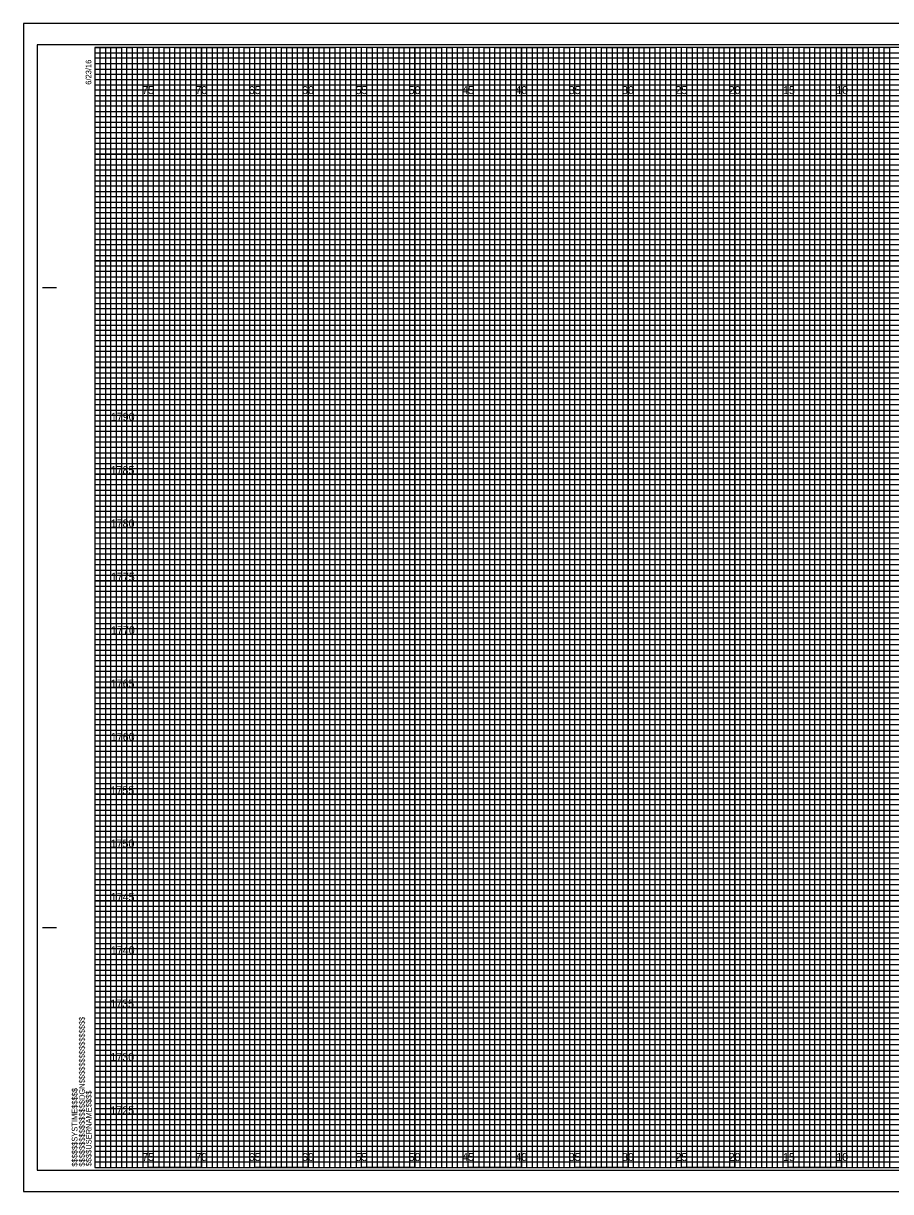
# Model space of a CAD drawing. Extents: x -7 to 162, y -2 to 547.
# Drawn here: x -6.7 to 74.6, y 107.7 to 217.2 of the extents above; entities that cross this region are included whole.
import ezdxf

# ---------------------------------------------------------------- set-up
doc = ezdxf.new("R2010")
doc.units = 0
for name, color, linetype in [('Prop XS Gore Control Minimum', 7, 'Continuous'), ('Prop XS Shoulder Borrow Shape', 7, 'Continuous'), ('Raster_Level_0', 7, 'Continuous'), ('Scratch_Level_3', 7, 'Continuous'), ('Sheet Cross Section CELL', 7, 'Continuous'), ('Sheet Cross Section Grid Minor 1 CELL', 7, 'Continuous'), ('Sheet Cross Section Grid Minor 2 CELL', 7, 'Continuous'), ('Sheet Cutting Line CELL', 7, 'Continuous'), ('Sheet DOT Grid CELL', 7, 'Continuous'), ('Sheet Plot Border Inside CELL', 7, 'Continuous'), ('Sheet Plot Border Outside CELL', 7, 'Continuous')]:
    doc.layers.add(name, color=color, linetype=linetype)

msp = doc.modelspace()

# ---------------------------------------------------------------- linework, layer by layer
at = {"layer": 'Prop XS Gore Control Minimum'}
for p, q in [((5, 215), (0, 215)), ((5, 110), (5, 215)), ((15, 215), (10, 215)), ((10, 215), (10, 110)), ((15, 110), (15, 215)), ((25, 215), (20, 215)), ((20, 215), (20, 110)), ((25, 110), (25, 215)), ((35, 215), (30, 215)), ((30, 215), (30, 110)), ((35, 110), (35, 215)), ((45, 215), (40, 215)), ((40, 215), (40, 110)), ((45, 110), (45, 215)), ((55, 215), (50, 215)), ((50, 215), (50, 110)), ((55, 110), (55, 215)), ((65, 215), (60, 215)), ((60, 215), (60, 110)), ((65, 110), (65, 215)), ((75, 215), (70, 215)), ((70, 215), (70, 110)), ((10, 110), (5, 110)), ((20, 110), (15, 110)), ((30, 110), (25, 110)), ((40, 110), (35, 110)), ((50, 110), (45, 110)), ((60, 110), (55, 110)), ((70, 110), (65, 110))]:
    msp.add_line(p, q, dxfattribs=at)
for points in [[(0, 210), (160, 210), (160, 205), (0, 205)], [(0, 200), (160, 200), (160, 195), (0, 195)], [(0, 190), (160, 190), (160, 185), (0, 185)], [(0, 180), (160, 180), (160, 175), (0, 175)], [(0, 170), (160, 170), (160, 165), (0, 165)], [(0, 160), (160, 160), (160, 155), (0, 155)], [(0, 150), (160, 150), (160, 145), (0, 145)], [(0, 140), (160, 140), (160, 135), (0, 135)], [(0, 130), (160, 130), (160, 125), (0, 125)], [(0, 120), (160, 120), (160, 115), (0, 115)]]:
    msp.add_lwpolyline(points, dxfattribs=at)
at = {"layer": 'Prop XS Shoulder Borrow Shape'}
for points in [[(0, 215), (2.5, 215), (2.5, 110), (7.5, 110), (7.5, 215), (12.5, 215), (12.5, 110), (17.5, 110), (17.5, 215), (22.5, 215), (22.5, 110), (27.5, 110), (27.5, 215), (32.5, 215), (32.5, 110), (37.5, 110), (37.5, 215), (42.5, 215), (42.5, 110), (47.5, 110), (47.5, 215), (52.5, 215), (52.5, 110), (57.5, 110), (57.5, 215), (62.5, 215), (62.5, 110), (67.5, 110), (67.5, 215), (72.5, 215), (72.5, 110), (77.5, 110)], [(0, 212.5), (137.5, 212.5)], [(0, 202.5), (160, 202.5), (160, 207.5), (0, 207.5)], [(0, 192.5), (160, 192.5), (160, 197.5), (0, 197.5)], [(0, 182.5), (160, 182.5), (160, 187.5), (0, 187.5)], [(0, 172.5), (160, 172.5), (160, 177.5), (0, 177.5)], [(0, 162.5), (160, 162.5), (160, 167.5), (0, 167.5)], [(0, 152.5), (160, 152.5), (160, 157.5), (0, 157.5)], [(0, 142.5), (160, 142.5), (160, 147.5), (0, 147.5)], [(0, 132.5), (160, 132.5), (160, 137.5), (0, 137.5)], [(0, 122.5), (160, 122.5), (160, 127.5), (0, 127.5)], [(0, 112.5), (160, 112.5), (160, 117.5), (0, 117.5)]]:
    msp.add_lwpolyline(points, dxfattribs=at)
at = {"layer": 'Sheet Cross Section CELL'}
for p, q in [((-4.9, 192.5), (-3.65, 192.5)), ((-4.85, 192.5), (-3.6, 192.5)), ((-4.9, 132.5), (-3.65, 132.5)), ((-4.85, 132.5), (-3.6, 132.5)), ((0, 110), (0, 110)), ((0, 110), (0, 110)), ((0, 110), (0, 110)), ((0, 110), (0, 110)), ((0, 110), (0, 110)), ((0, 110), (0, 110)), ((0, 110), (0, 110))]:
    msp.add_line(p, q, dxfattribs=at)
msp.add_lwpolyline([(160, 215), (0, 215), (0, 110), (160, 110)], close=True, dxfattribs=at)
at = {"layer": 'Sheet Cross Section Grid Minor 1 CELL'}
for p, q in [((0, 214.5), (130, 214.5)), ((130, 213.99), (0, 213.99)), ((0, 213.99), (0, 213.5)), ((0, 213.5), (130, 213.5)), ((130, 212.94), (0, 212.94)), ((0, 212.94), (0, 212)), ((0, 212), (160, 212))]:
    msp.add_line(p, q, dxfattribs=at)
for points in [[(0, 211.5), (135, 211.5), (160, 211.5), (160, 211), (0, 211)], [(0, 210.5), (160, 210.5), (160, 209.5), (0, 209.5)], [(0, 209), (160, 209), (160, 208.5), (0, 208.49)], [(0, 208), (160, 208), (160, 207), (0, 207)], [(0, 206.5), (160, 206.5), (160, 206), (0, 206)], [(0, 205.5), (160, 205.5), (160, 204.5), (0, 204.5)], [(0, 204), (160, 204), (160, 203.5), (0, 203.5)], [(0, 203), (160, 203), (160, 202), (0, 202)], [(0, 201.5), (160, 201.5), (160, 201), (0, 201)], [(0, 200.5), (160, 200.5), (160, 199.5), (0, 199.5)], [(0, 199), (160, 199), (160, 198.5), (0, 198.5)], [(0, 198), (160, 198), (160, 196.97), (160, 196.5), (160, 196), (0, 196)], [(0, 197), (160, 197), (160, 196.5), (0, 196.5)], [(0, 195.5), (160, 195.5), (160, 194.5), (0, 194.52)], [(0, 194.52), (160, 194.5), (160, 194), (0, 194)], [(0, 193.5), (160, 193.5), (160, 193), (0, 193)], [(0, 192), (160, 192), (160, 191.5), (0, 191.5)], [(0, 191), (160, 191), (160, 190.5), (0, 190.5)], [(-0.04, 189.44), (160, 189.44), (160, 188.94), (-0.04, 188.94)], [(0, 188.5), (160, 188.5), (160, 188), (0, 188)], [(0, 187), (160, 187), (160, 186.5), (0, 186.5)], [(0, 186), (160, 186), (160, 185.5), (0, 185.5)], [(0, 184.5), (160, 184.5), (160, 184), (0, 184)], [(0, 183.5), (160, 183.5), (160, 183), (0, 183)], [(0, 182), (160, 182), (160, 181.5), (0, 181.5)], [(0, 181), (160, 181), (160, 180.5), (0, 180.5)], [(0, 179.5), (160, 179.5), (160, 178.99), (0, 179)], [(0, 178.5), (160, 178.5), (160, 178), (0, 178)], [(0, 177), (160, 177), (160, 176.5), (0, 176.5)], [(0, 176), (160, 176), (160, 175.5), (0, 175.5)], [(0, 174.5), (160, 174.5), (160, 174), (0, 174)], [(0, 173.5), (160, 173.5), (160, 173), (0, 173)], [(0, 172), (160, 172), (160, 171.5), (0, 171.5)], [(0, 171), (160, 171), (160, 170.5), (0, 170.5)], [(0, 169.5), (160, 169.5), (160, 169), (0, 169)], [(0, 168.5), (160.03, 168.46), (160, 168), (0, 168)], [(0, 167), (160, 167), (160, 166.5), (0, 166.5)], [(0, 166), (160, 166), (160, 165.5), (0, 165.5)], [(0, 164.5), (160, 164.5), (160, 164), (0, 164)], [(0, 163.5), (160, 163.5), (160, 163), (0, 163)], [(0, 162), (160, 162), (160, 161.5), (0, 161.5)], [(0, 161), (160, 161), (160, 160.5), (0, 160.5)], [(0, 159.5), (160, 159.5), (160, 159), (0, 159)], [(0, 158.5), (160, 158.5), (160, 158), (0, 158)], [(0, 157), (160, 157), (160, 156.5), (0, 156.5)], [(0, 156), (160, 156), (160, 155.5), (0, 155.5)], [(0, 154.5), (160, 154.5), (160, 154), (0, 154)], [(0, 153.5), (160, 153.5), (160, 153), (0, 153)], [(0, 152), (160, 152), (160, 151.5), (0, 151.5)], [(0, 151), (160, 151), (160, 150.5), (0, 150.5)], [(0, 149.5), (160, 149.5), (160, 148.99), (0, 149)], [(0, 148.5), (160, 148.5), (160, 148), (0, 148)], [(0, 147), (160, 147), (160, 146.5), (0, 146.5)], [(0, 146), (160, 146), (160, 145.5), (0, 145.5)], [(0, 144.5), (160, 144.5), (160, 144), (0, 144)], [(0, 143.5), (160, 143.5), (160, 143), (0, 143)], [(0, 142), (160, 142), (160, 141.5), (0, 141.5)], [(0, 141), (160, 141), (160, 140.5), (0, 140.5)], [(0, 139.5), (160, 139.5), (160, 139), (0, 139)], [(0, 138.5), (160.03, 138.46), (160, 138), (0, 138)], [(0, 137), (160, 137), (160, 136.5), (0, 136.5)], [(0, 136), (160, 136), (160, 135.5), (0, 135.5)], [(0, 134.5), (160, 134.5), (160, 134), (0, 134)], [(0, 133.5), (160, 133.5), (160, 133), (0, 133)], [(0, 132), (160, 132), (160, 131.5), (0, 131.5)], [(0, 131), (160, 131), (160, 130.5), (0, 130.5)], [(0, 129.5), (160, 129.5), (160, 129), (0, 129)], [(0, 128.5), (160, 128.5), (160, 128), (0, 128)], [(0, 127), (160, 127), (160, 126.5), (0, 126.5)], [(0, 126), (160, 126), (160, 125.5), (0, 125.5)], [(0, 124.5), (160, 124.5), (160, 124), (0, 124)], [(0, 123.5), (160, 123.5), (160, 123), (0, 123)], [(0, 122), (160, 122), (160, 121.5), (0, 121.5)], [(0, 121), (160, 121), (160, 120.5), (0, 120.5)], [(0, 119.5), (160, 119.5), (160, 119), (0, 119)], [(0, 118.5), (160, 118.5), (160, 118), (0, 118)], [(0, 117), (160, 117), (160, 116.5), (0, 116.5)], [(0, 116), (160, 116), (160, 115.5), (0, 115.5)], [(0, 114.5), (160, 114.5), (160, 114), (0, 114)], [(0, 113.5), (160, 113.5), (160, 113), (0, 113)], [(0, 112), (160, 112), (160, 111.5), (0, 111.5)], [(0, 111), (160, 111), (160, 110.5), (0, 110.5)]]:
    msp.add_lwpolyline(points, dxfattribs=at)
at = {"layer": 'Sheet Cross Section Grid Minor 2 CELL'}
for points in [[(0, 110), (0.5, 110), (0.5, 215), (1, 215), (1, 110)], [(1, 110), (1.5, 110), (1.5, 215), (2, 215), (2, 110)], [(2.5, 110), (3, 110), (3, 215), (3.5, 215), (3.5, 110)], [(3.5, 110), (4, 110), (4, 215), (4.5, 215), (4.5, 110)], [(5, 110), (5.5, 110), (5.5, 215), (6, 215), (6, 110)], [(6, 110), (6.5, 110), (6.5, 215), (7, 215), (7, 110)], [(7.5, 110), (8, 110), (8, 215), (8.5, 215), (8.5, 110)], [(8.5, 110), (9, 110), (9, 215), (9.5, 215), (9.5, 110)], [(10, 110), (10.5, 110), (10.5, 215), (11, 215), (11, 110)], [(11, 110), (11.5, 110), (11.5, 215), (12, 215), (12, 110)], [(12.5, 110), (13, 110), (13, 215), (13.5, 215), (13.5, 110)], [(13.5, 110), (14, 110), (14, 215), (14.5, 215), (14.5, 110)], [(15, 110), (15.5, 110), (15.5, 215), (16, 215), (16, 110)], [(16, 110), (16.5, 110), (16.5, 215), (17, 215), (17, 110)], [(17.5, 110), (18, 110), (18, 215), (18.5, 215), (18.5, 110)], [(18.5, 110), (19, 110), (19, 215), (19.5, 215), (19.5, 110)], [(20, 110), (20.5, 110), (20.5, 215), (21, 215), (21, 110)], [(21, 110), (21.5, 110), (21.5, 215), (22, 215), (22, 110)], [(22.5, 110), (23, 110), (23, 215), (23.5, 215), (23.5, 110)], [(23.5, 110), (24, 110), (24, 215), (24.5, 215), (24.5, 110)], [(25, 110), (25.5, 110), (25.5, 215), (26, 215), (26, 110)], [(26, 110), (26.5, 110), (26.5, 215), (27, 215), (27, 110)], [(27.5, 110), (28, 110), (28, 215), (28.5, 215), (28.5, 110)], [(28.5, 110), (29, 110), (29, 215), (29.5, 215), (29.5, 110)], [(30, 110), (30.5, 110), (30.5, 215), (31, 215), (31, 110)], [(31, 110), (31.5, 110), (31.5, 215), (32, 215), (32, 110)], [(32.5, 110), (33, 110), (33, 215), (33.5, 215), (33.5, 110)], [(33.5, 110), (34, 110), (34, 215), (34.5, 215), (34.5, 110)], [(35, 110), (35.5, 110), (35.5, 215), (36, 215), (36, 110)], [(36, 110), (36.5, 110), (36.5, 215), (37, 215), (37, 110)], [(37.5, 110), (38, 110), (38, 215), (38.5, 215), (38.5, 110)], [(38.5, 110), (39, 110), (39, 215), (39.5, 215), (39.5, 110)], [(40, 110), (40.5, 110), (40.5, 215), (41, 215), (41, 110)], [(41, 110), (41.5, 110), (41.5, 215), (42, 215), (42, 110)], [(42.5, 110), (43, 110), (43, 215), (43.5, 215), (43.5, 110)], [(43.5, 110), (44, 110), (44, 215), (44.5, 215), (44.5, 110)], [(45, 110), (45.5, 110), (45.5, 215), (46, 215), (46, 110)], [(46, 110), (46.5, 110), (46.5, 215), (47, 215), (47, 110)], [(47.5, 110), (48, 110), (48, 215), (48.5, 215), (48.5, 110)], [(48.5, 110), (49, 110), (49, 215), (49.5, 215), (49.5, 110)], [(50, 110), (50.5, 110), (50.5, 215), (51, 215), (51, 110)], [(51, 110), (51.5, 110), (51.5, 215), (52, 215), (52, 110)], [(52.5, 110), (53, 110), (53, 215), (53.5, 215), (53.5, 110)], [(53.5, 110), (54, 110), (54, 215), (54.5, 215), (54.5, 110)], [(55, 110), (55.5, 110), (55.5, 215), (56, 215), (56, 110)], [(56, 110), (56.5, 110), (56.5, 215), (57, 215), (57, 110)], [(57.5, 110), (58, 110), (58, 215), (58.5, 215), (58.5, 110)], [(58.5, 110), (59, 110), (59, 215), (59.5, 215), (59.5, 110)], [(60, 110), (60.5, 110), (60.5, 215), (61, 215), (61, 110)], [(61, 110), (61.5, 110), (61.5, 215), (62, 215), (62, 110)], [(62.5, 110), (63, 110), (63, 215), (63.5, 215), (63.5, 110)], [(63.5, 110), (64, 110), (64, 215), (64.5, 215), (64.5, 110)], [(65, 110), (65.5, 110), (65.5, 215), (66, 215), (66, 110)], [(66, 110), (66.5, 110), (66.5, 215), (67, 215), (67, 110)], [(67.5, 110), (68, 110), (68, 215), (68.5, 215), (68.5, 110)], [(68.5, 110), (69, 110), (69, 215), (69.5, 215), (69.5, 110)], [(70, 110), (70.5, 110), (70.5, 215), (71, 215), (71, 110)], [(71, 110), (71.5, 110), (71.5, 215), (72, 215), (72, 110)], [(72.5, 110), (73, 110), (73, 215), (73.5, 215), (73.5, 110)], [(73.5, 110), (74, 110), (74, 215), (74.5, 215), (74.5, 110)]]:
    msp.add_lwpolyline(points, dxfattribs=at)
at = {"layer": 'Sheet Cutting Line CELL'}
for p, q in [((161.65, 217.25), (-6.7, 217.25)), ((-6.7, 217.25), (-6.7, 107.75)), ((-6.7, 107.75), (161.65, 107.75))]:
    msp.add_line(p, q, dxfattribs=at)
at = {"layer": 'Sheet DOT Grid CELL'}
for p, q in [((5, 110), (5, 215)), ((10, 110), (10, 215)), ((15, 110), (15, 215)), ((20, 110), (20, 215)), ((25, 110), (25, 215)), ((30, 110), (30, 215)), ((35, 110), (35, 215)), ((40, 110), (40, 215)), ((45, 110), (45, 215)), ((50, 110), (50, 215)), ((55, 110), (55, 215)), ((60, 110), (60, 215)), ((65, 110), (65, 215)), ((70, 110), (70, 215)), ((0, 210), (160, 210)), ((0, 205), (160, 205)), ((0, 200), (160, 200)), ((0, 195), (160, 195)), ((0, 190), (160, 190)), ((0, 185), (160, 185)), ((0, 180), (160, 180)), ((0, 175), (160, 175)), ((0, 170), (160, 170)), ((0, 165), (160, 165)), ((0, 160), (160, 160)), ((0, 155), (160, 155)), ((0, 150), (160, 150)), ((0, 145), (160, 145)), ((0, 140), (160, 140)), ((0, 135), (160, 135)), ((0, 130), (160, 130)), ((0, 125), (160, 125)), ((0, 120), (160, 120)), ((0, 115), (160, 115))]:
    msp.add_line(p, q, dxfattribs=at)
at = {"layer": 'Sheet Plot Border Inside CELL'}
msp.add_lwpolyline([(-5.4, 109.75), (161.2, 109.75), (161.2, 215.25), (-5.4, 215.25)], close=True, dxfattribs=at)
at = {"layer": 'Sheet Plot Border Outside CELL'}
msp.add_lwpolyline([(-6.7, 107.75), (161.65, 107.75), (161.65, 217.25), (-6.7, 217.25)], close=True, dxfattribs=at)

# ---------------------------------------------------------------- texts
at = {"layer": 'Raster_Level_0'}
for s, p in [('75', (4.44, 210.62)), ('70', (9.43, 210.62)), ('65', (14.44, 210.62)), ('60', (19.43, 210.62)), ('55', (24.44, 210.62)), ('50', (29.43, 210.62)), ('45', (34.44, 210.62)), ('40', (39.43, 210.62)), ('35', (44.44, 210.62)), ('30', (49.43, 210.62)), ('25', (54.44, 210.62)), ('20', (59.43, 210.62)), ('15', (64.53, 210.62)), ('10', (69.52, 210.62)), ('75', (4.44, 110.62)), ('70', (9.43, 110.62)), ('65', (14.44, 110.62)), ('60', (19.43, 110.62)), ('55', (24.44, 110.62)), ('50', (29.43, 110.62)), ('45', (34.44, 110.62)), ('40', (39.43, 110.62)), ('35', (44.44, 110.62)), ('30', (49.43, 110.62)), ('25', (54.44, 110.62)), ('20', (59.43, 110.62)), ('15', (64.53, 110.62)), ('10', (69.52, 110.62))]:
    msp.add_text(s, height=0.75, dxfattribs=at).set_placement(p)
at = {"layer": 'Scratch_Level_3'}
for s, p in [('1790', (1.5, 180)), ('1785', (1.48, 175)), ('1780', (1.49, 170)), ('1775', (1.51, 165)), ('1770', (1.52, 160)), ('1765', (1.49, 155)), ('1760', (1.5, 150)), ('1755', (1.47, 145)), ('1750', (1.48, 140)), ('1745', (1.49, 135)), ('1740', (1.5, 130)), ('1735', (1.45, 125)), ('1730', (1.46, 120)), ('1725', (1.46, 115))]:
    msp.add_text(s, height=0.75, dxfattribs=at).set_placement(p)
at = {"layer": 'Sheet Cross Section CELL'}
for s, p in [('6/23/16', (-0.33, 211.5)), ('$$$$$$$$$$$$$$$$DGN$$$$$$$$$$$$$$$$', (-0.94, 110.09)), ('$$$$$$SYSTIME$$$$$', (-1.63, 110.09)), ('$$$$USERNAME$$$$', (-0.31, 110.12))]:
    msp.add_text(s, height=0.525, rotation=90, dxfattribs=at).set_placement(p)

doc.saveas('drawing.dxf')
